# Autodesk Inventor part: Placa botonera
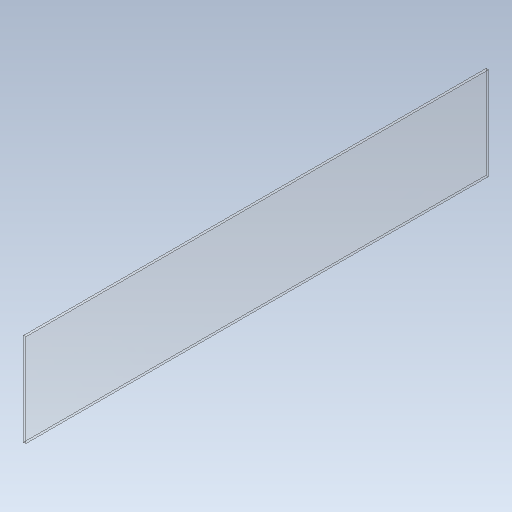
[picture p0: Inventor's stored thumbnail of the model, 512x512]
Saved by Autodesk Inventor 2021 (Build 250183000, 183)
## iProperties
Created: 2021-02
Part Number: Placa botonera
Material: Plástico PET
Document SubType Name: Modeling
Designer: ATOUZA
Density: 1.541 g/cm^3
Appearance: Policarbonato - Claro
Author: ATOUZA
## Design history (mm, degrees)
sketch "Boceto1"
  geometry: L1 (121.417, 308.504)-(1.417, 308.504); L2 (1.417, 308.504)-(1.417, -291.496); L3 (1.417, -291.496)-(121.417, -291.496); L4 (121.417, -291.496)-(121.417, 308.504); 1 further point
  constraints: 8 end point, 2 parallel, 1 horizontal, 1 perpendicular
  dimensions: "d0" = 600 distance of L3.end L1.start; "d1" = 120 distance of L1.start L1.end
extrude "Extrusión1" new body sketch "Boceto1" distance "d2" = 3; taper "d3" = 0 deg
node "Sólido1"
